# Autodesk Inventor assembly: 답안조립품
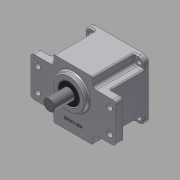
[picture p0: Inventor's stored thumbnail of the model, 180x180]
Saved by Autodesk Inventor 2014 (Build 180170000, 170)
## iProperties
Created: 2015-07
Part Number: 답안조립품
Document SubType Name: Assembly
Designer: Administrator
Author: Administrator
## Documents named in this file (12)
- C:\Users\Administrator\Desktop\450727V1007\답안조립품.iam
- C:\Users\Administrator\Desktop\450727V1007\본체.ipt
- C:\Users\Administrator\Desktop\450727V1007\커버.ipt
- C:\Users\Administrator\Desktop\450727V1007\베어링 608.ipt
- 베어링 608.ipt
- C:\Users\Administrator\Desktop\450727V1007\베어링 6003.ipt
- 베어링 6003.ipt
- C:\Users\Administrator\Desktop\450727V1007\오일실 17x32x8.ipt
- C:\Users\Administrator\Desktop\450727V1007\오일실 8x22x7.ipt
- C:\Users\Administrator\Desktop\450727V1007\메인축.ipt
- C:\Users\Administrator\Desktop\450727V1007\서브축.ipt
- C:\Users\Administrator\Desktop\450727V1007\M4x0.5x16.ipt
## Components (4 placed, 1 different names)
1. M4x0.5x12:1
2. M4x0.5x12:2
3. M4x0.5x12:3
4. M4x0.5x12:4
